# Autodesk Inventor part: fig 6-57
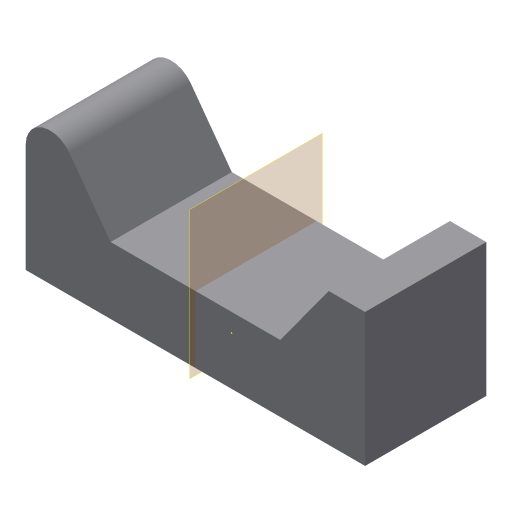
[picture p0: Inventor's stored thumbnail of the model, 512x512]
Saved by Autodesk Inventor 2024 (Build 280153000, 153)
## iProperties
Created: 2011-07
Part Number: fig 6-57
Material: Generic
Document SubType Name: Modeling
Designer: CadCim
Density: 1 g/cm^3
Appearance: Default
Author: CadCim
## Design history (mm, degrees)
sketch "Sketch2"
  geometry: L1 (3, -4)-(17, -4); L2 (17, -4)-(17, 7); L3 (17, 7)-(14, 7); L4 (14, 7)-(10, 1.5); L5 (10, 1.5)-(3, 1.5); L6 (3, -4)-(-11, -4); L7 (-11, -4)-(-11, 7); L8 (-11, 7)-(-8, 7); L9 (-8, 7)-(-4, 1.5); L10 (-4, 1.5)-(3, 1.5); 1 further point
  constraints: 20 end point, 2 parallel, 1 perpendicular
extrude "Extrusion1" new body sketch "Sketch2" distance "d0" = 10; taper "d1" = 0 deg
fillet "Fillet1" dims "d2" = 2
workplane "Work Plane1"
body "Solid1"
sketch "Sketch1"
  geometry: 1 further point
